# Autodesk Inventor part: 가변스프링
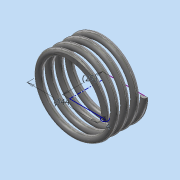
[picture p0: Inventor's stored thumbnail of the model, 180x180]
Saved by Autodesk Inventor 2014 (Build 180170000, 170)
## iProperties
Created: 2023-07
Part Number: 가변스프링
Material: 스테인레스 스틸
Document SubType Name: Modeling
Designer: dg
Density: 8.08 g/cm^3
Appearance: 반연마
Mass: 54.2915 g
Surface Area: 69.0088 cm^2
Volume: 6.71924 cm^3
Author: dg
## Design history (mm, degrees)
sketch "스케치1"
  geometry: L1 (22, 0)-(0, 0); L2 (0, 0)-(0, 25); L3 (0, 25)-(22, 25); C1 r 2 at (22, 0)
  constraints: 6 end point, 2 parallel, 1 centre point, 1 coincident, 1 horizontal, 1 perpendicular
  dimensions: "d0" = 25 distance of L1.end L2.end (derived); "d1" = 4 diameter of C1; "d2" = 44 diameter of L1.start L2
feature "코일1" pitch "d3" = 10; turns "d5" = 4; dims "d4" = 25 (= d0), "d6" = 0, angle "d7" = 90 deg, angle "d8" = 90 deg, "d9" = 0, "d10" = 0
node "작업 평면1"
node "작업 평면2"
feature "분할1"
feature "분할2"
node "솔리드1"
other parameters: "d11" = 0, "d12" = 90 deg
